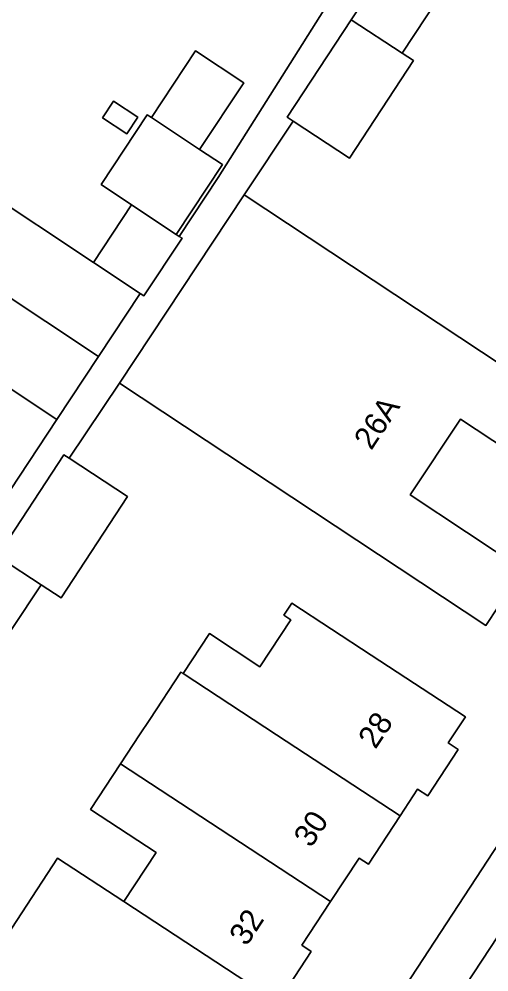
# Model space of a CAD drawing. Extents: x 159279 to 160377, y 384531 to 385888.
# Drawn here: x 159585.63 to 159606.48, y 385239.48 to 385281.77 of the extents above; entities that cross this region are included whole.
import ezdxf

# ---------------------------------------------------------------- set-up
doc = ezdxf.new("R2010")
doc.units = 0
for name, color, linetype in [('IMGEO_Erf', 7, 'Continuous'), ('IMGEO_Pand', 7, 'Continuous'), ('IMGEO_Pand_nummerreeks', 7, 'Continuous'), ('IMGEO_Parkeervlak_open', 7, 'Continuous'), ('IMGEO_Voetpad_open', 7, 'Continuous')]:
    doc.layers.add(name, color=color, linetype=linetype)

msp = doc.modelspace()

# ---------------------------------------------------------------- linework, layer by layer
at = {"layer": 'IMGEO_Erf'}
for points in [[(159583.936, 385274.271), (159588.933, 385270.962), (159590.627, 385273.52), (159589.268, 385274.42), (159591.319, 385277.519), (159591.507, 385277.395), (159593.468, 385280.356), (159595.601, 385278.944), (159593.64, 385275.982), (159594.657, 385275.31), (159592.605, 385272.211), (159592.738, 385272.123), (159594.468, 385274.737), (159602.168, 385286.962)], [(159604.755, 385283.497), (159602.633, 385280.26), (159603.139, 385279.928), (159600.299, 385275.595), (159597.788, 385277.242), (159595.623, 385273.972), (159611.874, 385263.213), (159610.218, 385260.711), (159605.224, 385264.018), (159602.994, 385260.65), (159607.988, 385257.343), (159606.337, 385254.849), (159590.086, 385265.608), (159587.849, 385262.28), (159590.448, 385260.573), (159587.497, 385256.076), (159586.62, 385256.652), (159583.993, 385252.744)], [(159574.014, 385243.829), (159587.308, 385264.003), (159580.238, 385268.684)], [(159584.153, 385239.678), (159587.341, 385244.529), (159590.282, 385242.599), (159591.713, 385244.781), (159588.806, 385246.687), (159590.134, 385248.713), (159590.978, 385250), (159591.429, 385250.688), (159592.807, 385252.79), (159592.914, 385252.72), (159594.079, 385254.496), (159596.323, 385253.024), (159597.69, 385255.109), (159597.381, 385255.313), (159597.734, 385255.852), (159601.257, 385253.542), (159605.438, 385250.8), (159604.913, 385250), (159604.678, 385249.641), (159605.113, 385249.356), (159603.764, 385247.298), (159603.315, 385247.592), (159602.536, 385246.404), (159601.133, 385244.264), (159600.719, 385244.535), (159599.45, 385242.6), (159598.181, 385240.665), (159598.597, 385240.392), (159597.108, 385238.121)], [(159581.668, 385206.619), (159610.074, 385250)]]:
    msp.add_lwpolyline(points, dxfattribs=at)
msp.add_lwpolyline([(159590.896, 385277.409), (159590.409, 385276.674), (159589.335, 385277.385), (159589.822, 385278.12)], close=True, dxfattribs=at)
at = {"layer": 'IMGEO_Pand'}
for points in [[(159602.496, 385284.978), (159600.374, 385281.74), (159602.633, 385280.26), (159604.755, 385283.497)], [(159602.633, 385280.26), (159600.374, 385281.74), (159597.534, 385277.408), (159597.788, 385277.242), (159600.299, 385275.595), (159603.139, 385279.928)], [(159591.507, 385277.395), (159593.64, 385275.982), (159595.601, 385278.944), (159593.468, 385280.356)], [(159589.335, 385277.385), (159590.409, 385276.674), (159590.896, 385277.409), (159589.822, 385278.12)], [(159593.64, 385275.982), (159591.507, 385277.395), (159591.319, 385277.519), (159589.268, 385274.42), (159590.627, 385273.52), (159592.605, 385272.211), (159594.657, 385275.31)], [(159582.087, 385271.477), (159589.157, 385266.797), (159591.007, 385269.59), (159588.933, 385270.962), (159583.936, 385274.271)], [(159607.988, 385257.343), (159602.994, 385260.65), (159605.224, 385264.018), (159610.218, 385260.711), (159611.874, 385263.213), (159595.623, 385273.972), (159590.086, 385265.608), (159606.337, 385254.849)], [(159592.738, 385272.123), (159592.605, 385272.211), (159590.627, 385273.52), (159588.933, 385270.962), (159591.007, 385269.59), (159591.174, 385269.479), (159592.867, 385272.037)], [(159582.087, 385271.477), (159580.238, 385268.684), (159587.308, 385264.003), (159589.157, 385266.797)], [(159587.849, 385262.28), (159587.617, 385262.432), (159584.665, 385257.935), (159584.847, 385257.815), (159586.62, 385256.652), (159587.497, 385256.076), (159590.448, 385260.573)], [(159586.62, 385256.652), (159584.847, 385257.815), (159584.665, 385257.935), (159582.081, 385253.999), (159583.993, 385252.744)], [(159597.381, 385255.313), (159597.69, 385255.109), (159596.323, 385253.024), (159594.079, 385254.496), (159592.914, 385252.72), (159597.052, 385250), (159602.536, 385246.404), (159603.315, 385247.592), (159603.764, 385247.298), (159605.113, 385249.356), (159604.678, 385249.641), (159604.913, 385250), (159605.438, 385250.8), (159601.257, 385253.542), (159597.734, 385255.852)], [(159590.978, 385250), (159590.134, 385248.713), (159599.45, 385242.6), (159600.719, 385244.535), (159601.133, 385244.264), (159602.536, 385246.404), (159597.052, 385250), (159592.914, 385252.72), (159592.807, 385252.79), (159591.429, 385250.688)], [(159590.134, 385248.713), (159588.806, 385246.687), (159591.713, 385244.781), (159590.282, 385242.599), (159597.108, 385238.121), (159598.597, 385240.392), (159598.181, 385240.665), (159599.45, 385242.6)], [(159590.282, 385242.599), (159587.341, 385244.529), (159584.153, 385239.678), (159593.512, 385233.539), (159595.208, 385236.126), (159595.622, 385235.855), (159597.108, 385238.121)]]:
    msp.add_lwpolyline(points, close=True, dxfattribs=at)
at = {"layer": 'IMGEO_Parkeervlak_open'}
msp.add_lwpolyline([(159610.441, 385246.475), (159601.888, 385233.471)], dxfattribs=at)
at = {"layer": 'IMGEO_Voetpad_open'}
for points in [[(159602.168, 385286.962), (159594.468, 385274.737), (159592.738, 385272.123), (159592.867, 385272.037), (159591.174, 385269.479), (159591.007, 385269.59), (159589.157, 385266.797), (159587.308, 385264.003), (159574.014, 385243.829)], [(159584.665, 385257.935), (159587.617, 385262.432), (159587.849, 385262.28), (159590.086, 385265.608), (159595.623, 385273.972), (159597.788, 385277.242), (159597.534, 385277.408), (159600.374, 385281.74), (159602.496, 385284.978)], [(159629.433, 385279.565), (159610.074, 385250), (159581.668, 385206.619), (159579.129, 385202.804), (159579.823, 385202.444), (159580.465, 385202.468), (159581.102, 385202.549), (159581.729, 385202.687), (159582.342, 385202.88), (159582.935, 385203.127), (159583.503, 385203.426), (159584.042, 385203.775), (159584.548, 385204.17), (159585.017, 385204.609), (159585.445, 385205.089), (159585.828, 385205.604), (159585.943, 385205.78), (159587.459, 385207.776), (159587.804, 385208.303), (159590.541, 385212.477)], [(159601.888, 385233.471), (159610.441, 385246.475)]]:
    msp.add_lwpolyline(points, dxfattribs=at)

# ---------------------------------------------------------------- texts
at = {"layer": 'IMGEO_Pand_nummerreeks'}
for s, rotation, p in [('26A', 56.4909, (159601.259, 385262.594)), ('28', 56.368, (159601.444, 385249.328)), ('30', 56.7501, (159598.589, 385244.951)), ('32', 56.7515, (159595.727, 385240.584))]:
    msp.add_text(s, height=1, rotation=rotation, dxfattribs=at).set_placement(p)

doc.saveas('drawing.dxf')
